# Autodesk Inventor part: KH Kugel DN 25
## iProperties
Shininess: 64.0
Length Units: 11269
Angle Units: 11279
Time Units: 11290
Mass Units: 11283
Length Display Precision: 3
Angle Display Precision: 2
Compacted: True
Part Number: KH Kugel DN 25
Document SubType Name: Modeling
Created: 2004-09
Material: Messing (weiches, gelbes Messing)
Designer: AG
Manufacturer: Standard
Standards Organization: Custom
Density: 0.0
Volumn: 0.0
Area: 0.0
PropertySet Name: Model Information
Control State: 0
Master: False
Checked Out: False
Author: AG
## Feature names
1. Drehung1 [Revolution]
2. Extrusion1
3. Rundung1 [Fillet]
4. Extrusion2
